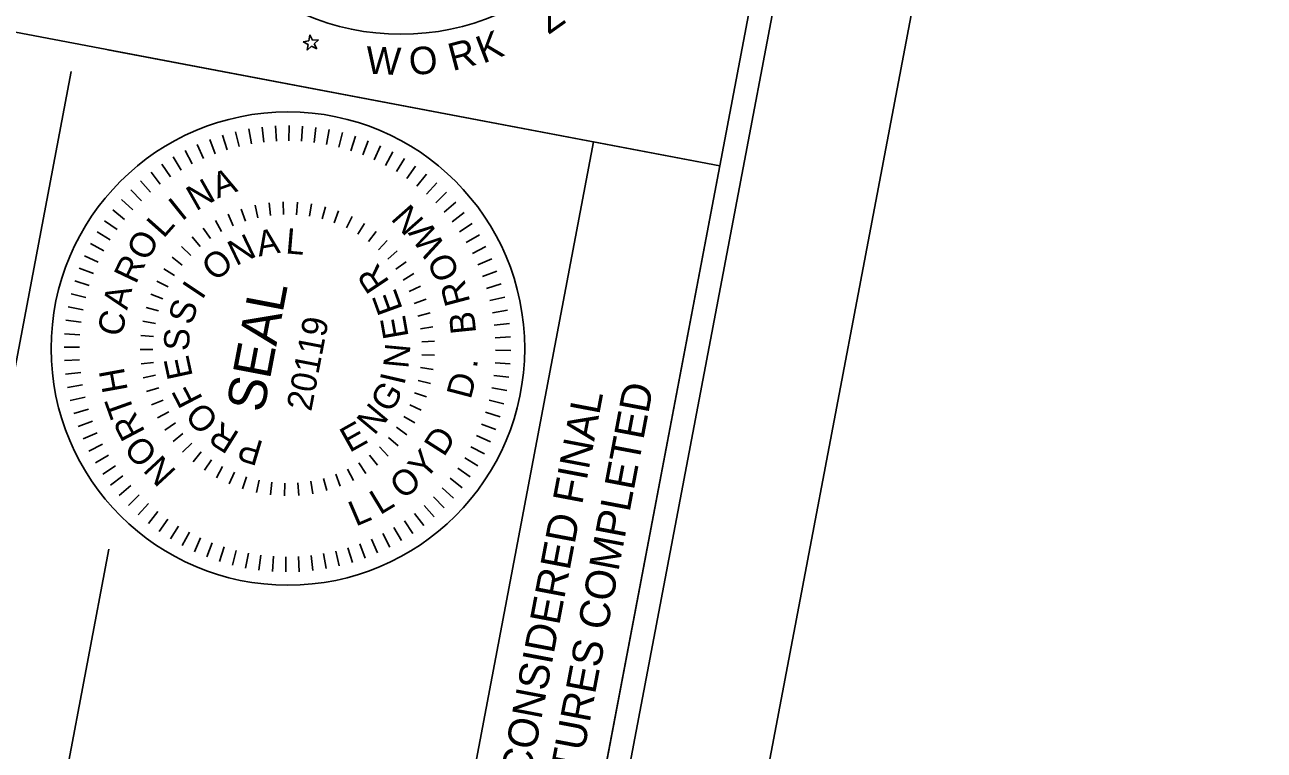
# Model space of a CAD drawing. Extents: x 1615680 to 1617075, y 898420 to 901168.
# Drawn here: x 1616848.5 to 1617075.3, y 900488.2 to 900621.1 of the extents above; entities that cross this region are included whole.
import ezdxf

# ---------------------------------------------------------------- set-up
doc = ezdxf.new("R2010")
doc.units = 0
for name, color, linetype in [('Default', 7, 'Continuous'), ('DEV BORDER CELL', 7, 'Continuous'), ('DEV DOT SWIRL SEAL CELL', 7, 'Continuous'), ('Sheet Plot Border Outside CELL', 7, 'Continuous'), ('Sheet Sticker Exception Certification CELL', 7, 'Continuous'), ('Text', 7, 'Continuous')]:
    doc.layers.add(name, color=color, linetype=linetype)

msp = doc.modelspace()

# ---------------------------------------------------------------- linework, layer by layer
at = {"layer": 'Default'}
for p, q in [((1616889.49, 900601.99), (1616889.97, 900599.25)), ((1616891.93, 900602.35), (1616892.24, 900599.58)), ((1616894.39, 900602.55), (1616894.54, 900599.77)), ((1616896.86, 900602.61), (1616896.84, 900599.82)), ((1616899.33, 900602.51), (1616899.14, 900599.74)), ((1616901.78, 900602.27), (1616901.43, 900599.51)), ((1616882.35, 900600.06), (1616883.32, 900597.45)), ((1616884.69, 900600.85), (1616885.5, 900598.18)), ((1616887.07, 900601.49), (1616887.72, 900598.78)), ((1616904.22, 900601.88), (1616903.7, 900599.15)), ((1616906.64, 900601.35), (1616905.95, 900598.65)), ((1616909.01, 900600.67), (1616908.16, 900598.01)), ((1616911.34, 900599.85), (1616910.33, 900597.25)), ((1616877.83, 900598.07), (1616879.11, 900595.59)), ((1616880.06, 900599.13), (1616881.18, 900596.58)), ((1616913.61, 900598.89), (1616912.45, 900596.35)), ((1616915.82, 900597.79), (1616914.51, 900595.33)), ((1616873.59, 900595.54), (1616875.15, 900593.24)), ((1616875.67, 900596.87), (1616877.1, 900594.47)), ((1616917.96, 900596.56), (1616916.5, 900594.18)), ((1616920.02, 900595.2), (1616918.43, 900592.92)), ((1616871.59, 900594.09), (1616873.29, 900591.89)), ((1616922.01, 900593.73), (1616920.27, 900591.54)), ((1616867.87, 900590.85), (1616869.82, 900588.86)), ((1616869.68, 900592.52), (1616871.51, 900590.43)), ((1616923.89, 900592.13), (1616922.03, 900590.06)), ((1616866.17, 900589.06), (1616868.24, 900587.2)), ((1616893.19, 900588.46), (1616893.48, 900586.16)), ((1616895.78, 900588.66), (1616895.85, 900586.34)), ((1616898.39, 900588.61), (1616898.23, 900586.3)), ((1616900.97, 900588.31), (1616900.59, 900586.02)), ((1616925.68, 900590.42), (1616923.69, 900588.47)), ((1616927.35, 900588.62), (1616925.26, 900586.78)), ((1616864.57, 900587.18), (1616866.75, 900585.44)), ((1616885.68, 900586.38), (1616886.63, 900584.26)), ((1616888.11, 900587.31), (1616888.85, 900585.11)), ((1616890.62, 900588.01), (1616891.14, 900585.75)), ((1616903.52, 900587.76), (1616902.92, 900585.52)), ((1616905.1, 900584.82), (1616905.91, 900587)), ((1616928.92, 900586.7), (1616926.72, 900585)), ((1616863.1, 900585.2), (1616865.37, 900583.6)), ((1616881.15, 900583.83), (1616882.48, 900581.92)), ((1616883.36, 900585.21), (1616884.49, 900583.19)), ((1616908.39, 900585.94), (1616907.37, 900583.86)), ((1616910.67, 900584.69), (1616909.45, 900582.71)), ((1616930.37, 900584.71), (1616928.07, 900583.14)), ((1616861.73, 900583.14), (1616864.11, 900581.67)), ((1616879.09, 900582.24), (1616880.6, 900580.47)), ((1616912.81, 900583.22), (1616911.41, 900581.37)), ((1616914.81, 900581.55), (1616913.24, 900579.84)), ((1616931.69, 900582.62), (1616929.3, 900581.2)), ((1616860.51, 900581), (1616862.97, 900579.68)), ((1616877.19, 900580.46), (1616878.87, 900578.85)), ((1616916.64, 900579.69), (1616914.91, 900578.14)), ((1616932.89, 900580.46), (1616930.42, 900579.19)), ((1616859.41, 900578.78), (1616861.94, 900577.62)), ((1616875.48, 900578.5), (1616877.29, 900577.06)), ((1616918.28, 900577.67), (1616916.41, 900576.3)), ((1616933.96, 900578.24), (1616931.41, 900577.11)), ((1616858.45, 900576.51), (1616861.05, 900575.5)), ((1616873.96, 900576.39), (1616875.91, 900575.13)), ((1616919.72, 900575.5), (1616917.72, 900574.31)), ((1616934.89, 900575.95), (1616932.27, 900574.98)), ((1616857.63, 900574.18), (1616860.28, 900573.33)), ((1616872.65, 900574.14), (1616874.71, 900573.07)), ((1616920.94, 900573.2), (1616918.84, 900572.21)), ((1616935.68, 900573.61), (1616933.01, 900572.8)), ((1616856.95, 900571.81), (1616859.65, 900571.12)), ((1616871.56, 900571.77), (1616873.72, 900570.91)), ((1616921.93, 900570.8), (1616919.74, 900570.01)), ((1616936.32, 900571.22), (1616933.61, 900570.58)), ((1616856.41, 900569.4), (1616859.15, 900568.87)), ((1616870.71, 900569.31), (1616872.94, 900568.66)), ((1616922.69, 900568.3), (1616920.43, 900567.74)), ((1616936.82, 900568.81), (1616934.08, 900568.32)), ((1616856.02, 900566.96), (1616858.78, 900566.6)), ((1616870.1, 900566.78), (1616872.38, 900566.35)), ((1616872.38, 900566.35), (1616870.1, 900566.78)), ((1616923.2, 900565.75), (1616920.9, 900565.4)), ((1616937.18, 900566.37), (1616934.4, 900566.05)), ((1616855.78, 900564.5), (1616858.56, 900564.31)), ((1616869.74, 900564.2), (1616872.05, 900563.99)), ((1616937.38, 900563.9), (1616934.6, 900563.76)), ((1616855.69, 900562.03), (1616858.47, 900562.01)), ((1616869.62, 900561.61), (1616871.94, 900561.61)), ((1616923.46, 900563.16), (1616921.14, 900563.04)), ((1616937.44, 900561.43), (1616934.65, 900561.46)), ((1616855.74, 900559.57), (1616858.52, 900559.71)), ((1616869.76, 900559.01), (1616872.07, 900559.24)), ((1616923.48, 900560.56), (1616921.16, 900560.66)), ((1616937.34, 900558.97), (1616934.57, 900559.16)), ((1616855.95, 900557.1), (1616858.72, 900557.42)), ((1616870.15, 900556.43), (1616872.43, 900556.89)), ((1616923.24, 900557.97), (1616920.94, 900558.29)), ((1616937.1, 900556.51), (1616934.34, 900556.87)), ((1616856.3, 900554.66), (1616859.05, 900555.14)), ((1616870.78, 900553.91), (1616873, 900554.58)), ((1616922.75, 900555.41), (1616920.49, 900555.95)), ((1616936.71, 900554.07), (1616933.98, 900554.59)), ((1616856.81, 900552.24), (1616859.51, 900552.89)), ((1616871.66, 900551.45), (1616873.81, 900552.34)), ((1616922.02, 900552.91), (1616919.82, 900553.67)), ((1616936.18, 900551.66), (1616933.48, 900552.35)), ((1616857.45, 900549.86), (1616860.12, 900550.67)), ((1616872.77, 900549.1), (1616874.82, 900550.19)), ((1616918.93, 900551.45), (1616921.04, 900550.48)), ((1616935.49, 900549.29), (1616932.84, 900550.13)), ((1616858.24, 900547.52), (1616860.85, 900548.49)), ((1616874.1, 900546.86), (1616876.04, 900548.15)), ((1616919.85, 900548.19), (1616917.84, 900549.36)), ((1616934.68, 900546.96), (1616932.08, 900547.96)), ((1616859.17, 900545.23), (1616861.71, 900546.36)), ((1616875.64, 900544.76), (1616877.44, 900546.23)), ((1616916.81, 900543.96), (1616915.06, 900545.5)), ((1616918.43, 900546), (1616916.54, 900547.36)), ((1616933.71, 900544.69), (1616931.18, 900545.84)), ((1616860.23, 900543.01), (1616862.71, 900544.28)), ((1616877.37, 900542.82), (1616879.03, 900544.45)), ((1616915, 900542.09), (1616913.41, 900543.79)), ((1616932.62, 900542.47), (1616930.15, 900543.78)), ((1616861.43, 900540.84), (1616863.82, 900542.27)), ((1616879.29, 900541.06), (1616880.78, 900542.84)), ((1616881.36, 900539.49), (1616882.67, 900541.41)), ((1616910.88, 900538.92), (1616909.65, 900540.88)), ((1616913.02, 900540.4), (1616911.6, 900542.24)), ((1616931.39, 900540.33), (1616929.01, 900541.79)), ((1616862.75, 900538.76), (1616865.06, 900540.33)), ((1616864.2, 900536.76), (1616866.41, 900538.46)), ((1616883.58, 900538.13), (1616884.7, 900540.16)), ((1616885.92, 900536.98), (1616886.84, 900539.12)), ((1616906.23, 900536.59), (1616905.4, 900538.76)), ((1616908.62, 900537.64), (1616907.58, 900539.72)), ((1616930.03, 900538.27), (1616927.75, 900539.87)), ((1616865.77, 900534.85), (1616867.87, 900536.68)), ((1616888.36, 900536.07), (1616889.06, 900538.28)), ((1616890.87, 900535.4), (1616891.37, 900537.67)), ((1616893.44, 900534.97), (1616893.71, 900537.28)), ((1616896.04, 900534.8), (1616896.08, 900537.12)), ((1616898.64, 900534.87), (1616898.46, 900537.19)), ((1616901.23, 900535.2), (1616900.82, 900537.49)), ((1616903.76, 900535.78), (1616903.14, 900538.01)), ((1616926.96, 900534.4), (1616924.89, 900536.27)), ((1616928.55, 900536.29), (1616926.37, 900538.02)), ((1616867.45, 900533.04), (1616869.43, 900535)), ((1616925.25, 900532.62), (1616923.3, 900534.6)), ((1616869.23, 900531.34), (1616871.1, 900533.41)), ((1616871.12, 900529.74), (1616872.85, 900531.92)), ((1616923.44, 900530.94), (1616921.61, 900533.04)), ((1616873.1, 900528.27), (1616874.69, 900530.55)), ((1616919.53, 900527.93), (1616917.97, 900530.23)), ((1616921.53, 900529.37), (1616919.83, 900531.58)), ((1616875.16, 900526.91), (1616876.62, 900529.28)), ((1616877.3, 900525.68), (1616878.61, 900528.14)), ((1616879.52, 900524.58), (1616880.67, 900527.11)), ((1616915.29, 900525.4), (1616914.02, 900527.88)), ((1616917.45, 900526.6), (1616916.03, 900528.99)), ((1616881.79, 900523.62), (1616882.79, 900526.22)), ((1616884.12, 900522.8), (1616884.96, 900525.45)), ((1616886.49, 900522.12), (1616887.17, 900524.82)), ((1616908.44, 900522.62), (1616907.63, 900525.29)), ((1616910.78, 900523.41), (1616909.81, 900526.02)), ((1616913.07, 900524.34), (1616911.94, 900526.88)), ((1616888.9, 900521.58), (1616889.42, 900524.32)), ((1616891.34, 900521.19), (1616891.7, 900523.96)), ((1616893.8, 900520.95), (1616893.99, 900523.73)), ((1616896.26, 900520.86), (1616896.28, 900523.64)), ((1616898.73, 900520.91), (1616898.59, 900523.7)), ((1616901.19, 900521.12), (1616900.88, 900523.89)), ((1616903.63, 900521.47), (1616903.15, 900524.22)), ((1616906.05, 900521.98), (1616905.41, 900524.69))]:
    msp.add_line(p, q, dxfattribs=at)
at = {"layer": 'DEV BORDER CELL'}
for p, q in [((1616863.68, 900616.49), (1616975.68, 900595.23)), ((1616829.71, 900468.75), (1616857, 900612.52)), ((1616849, 900446.64), (1616863.88, 900525.03))]:
    msp.add_line(p, q, dxfattribs=at)
for points in [[(1616014.55, 901139.21), (1615734.74, 899665.53), (1616766.32, 899469.67), (1617046.12, 900943.35)], [(1616840.59, 900620.87), (1616861.86, 900732.87), (1616996.95, 900707.23), (1616975.68, 900595.22)], [(1616803.28, 900424.35), (1616840.59, 900620.87), (1616975.68, 900595.22), (1616938.37, 900398.7)]]:
    msp.add_lwpolyline(points, close=True, dxfattribs=at)
msp.add_circle((1616896.65, 900561.78), 43.34, dxfattribs=at)
at = {"layer": 'DEV DOT SWIRL SEAL CELL'}
for p, q in [((1616900.47, 900618.15), (1616899.42, 900617.98)), ((1616899.42, 900617.98), (1616900.35, 900617.48)), ((1616900.67, 900619.21), (1616900.47, 900618.15)), ((1616901.14, 900618.23), (1616900.67, 900619.21)), ((1616901.14, 900618.23), (1616900.68, 900619.22)), ((1616902.23, 900618.35), (1616901.14, 900618.23)), ((1616902.23, 900618.35), (1616901.14, 900618.23)), ((1616901.43, 900617.6), (1616902.23, 900618.35)), ((1616901.43, 900617.6), (1616902.23, 900618.35)), ((1616900.35, 900617.48), (1616900.14, 900616.42)), ((1616900.14, 900616.42), (1616900.94, 900617.16)), ((1616900.94, 900617.16), (1616901.91, 900616.65)), ((1616901.91, 900616.65), (1616901.43, 900617.6))]:
    msp.add_line(p, q, dxfattribs=at)
at = {"layer": 'Sheet Plot Border Outside CELL'}
for points in [[(1616760.47, 899304.87), (1615679.78, 899510.06), (1615994.65, 901168.43), (1617075.34, 900963.24)], [(1616760.47, 899304.87), (1617075.34, 900963.24), (1615994.65, 901168.43), (1615679.78, 899510.06)]]:
    msp.add_lwpolyline(points, close=True, dxfattribs=at)
at = {"layer": 'Sheet Sticker Exception Certification CELL'}
for p, q in [((1616915.28, 900403.08), (1616952.59, 900599.61)), ((1616952.6, 900599.61), (1616975.69, 900595.22)), ((1616975.68, 900595.22), (1616938.37, 900398.7))]:
    msp.add_line(p, q, dxfattribs=at)
at = {"layer": 'Text'}
msp.add_circle((1616917.34, 900664.32), 44.97, dxfattribs=at)

# ---------------------------------------------------------------- texts
at = {"layer": 'Default'}
for s, height, rotation, p in [('N', 4.64, 29.481, (1616879.8, 900586.88)), ('A', 4.64, 19.7134, (1616883.74, 900589.24)), ('I', 4.64, 38.7754, (1616877.22, 900585)), ('N', 4.64, 131.4034, (1616921.77, 900585.19)), ('L', 4.64, 48.3509, (1616873.87, 900581.83)), ('L', 4.64, 355.067, (1616896.11, 900579.23)), ('W', 4.64, 122.5208, (1616925.62, 900580.49)), ('O', 4.64, 61.4872, (1616870.95, 900577.58)), ('N', 4.64, 25.6595, (1616887.11, 900576.83)), ('A', 4.64, 10.3632, (1616891.32, 900578.61)), ('O', 4.64, 40.9557, (1616883.39, 900573.9)), ('R', 4.64, 64.544, (1616868.8, 900573.42)), ('R', 4.64, 123.7612, (1616915.36, 900573.97)), ('O', 4.64, 113.6381, (1616928.19, 900575.35)), ('A', 4.64, 76.5533, (1616867.21, 900568.72)), ('I', 4.64, 56.252, (1616880.91, 900570.56)), ('SEAL', 6.965, 79.1963, (1616892.17, 900549.87)), ('E', 4.64, 109.9902, (1616917.71, 900569.02)), ('R', 4.64, 104.8155, (1616930.05, 900570.31)), ('S', 4.64, 71.5482, (1616879, 900565.9)), ('C', 4.64, 76.5533, (1616866.16, 900563.75)), ('B', 4.64, 95.813, (1616931.11, 900564.65)), ('20119', 4.64, 79.1963, (1616900.91, 900550.14)), ('E', 4.64, 100.0043, (1616918.76, 900563.97)), ('S', 4.64, 86.8445, (1616878.51, 900561.28)), ('N', 4.64, 84.6122, (1616918.68, 900558.01)), ('E', 4.64, 102.1407, (1616879.26, 900556.7)), ('.', 4.64, 83.0287, (1616931.23, 900558.08)), ('H', 4.64, 100.264, (1616867.36, 900554.13)), ('I', 4.64, 76.9825, (1616917.93, 900554.94)), ('D', 4.64, 75.2863, (1616930.09, 900552.34)), ('F', 4.64, 117.437, (1616881.15, 900552.56)), ('G', 4.64, 58.8877, (1616915.44, 900549.79)), ('T', 4.64, 109.6959, (1616868.65, 900550.08)), ('R', 4.64, 117.8569, (1616870.61, 900546.53)), ('O', 4.64, 132.7332, (1616884.24, 900548.83)), ('N', 4.64, 50.1215, (1616912.45, 900545.74)), ('R', 4.64, 148.0295, (1616887.99, 900546.25)), ('E', 4.64, 29.2664, (1616907.92, 900542.64)), ('O', 4.64, 130.9136, (1616873.05, 900542.64)), ('D', 4.64, 57.491, (1616925.2, 900541.79)), ('P', 4.64, 163.3257, (1616892.38, 900544.69)), ('Y', 4.64, 48.5185, (1616921.72, 900537.53)), ('N', 4.64, 132.8731, (1616876.4, 900539.29)), ('O', 4.64, 39.8459, (1616917.75, 900533.99)), ('L', 4.64, 31.2032, (1616913.5, 900531.22)), ('L', 4.64, 23.1314, (1616909.05, 900529.14))]:
    msp.add_text(s, height=height, rotation=rotation, dxfattribs=at).set_placement(p)
at = {"layer": 'Sheet Sticker Exception Certification CELL'}
for s, p in [('UNLESS ALL SIGNATURES COMPLETED', (1616937.07, 900415.23)), ('DOCUMENT NOT CONSIDERED FINAL', (1616929.37, 900421.85))]:
    msp.add_text(s, height=5.5, rotation=79.2494, dxfattribs=at).set_placement(p)
at = {"layer": 'Text'}
for s, rotation, p in [('Z', 35.4181, (1616944.38, 900619.21)), ('K', 21.0412, (1616932.34, 900613.91)), ('R', 14.8034, (1616926.77, 900612.58)), ('W', 357.3994, (1616910.86, 900612.13)), ('O', 6.3641, (1616919.07, 900611.76))]:
    msp.add_text(s, height=5.04, rotation=rotation, dxfattribs=at).set_placement(p)

doc.saveas('drawing.dxf')
